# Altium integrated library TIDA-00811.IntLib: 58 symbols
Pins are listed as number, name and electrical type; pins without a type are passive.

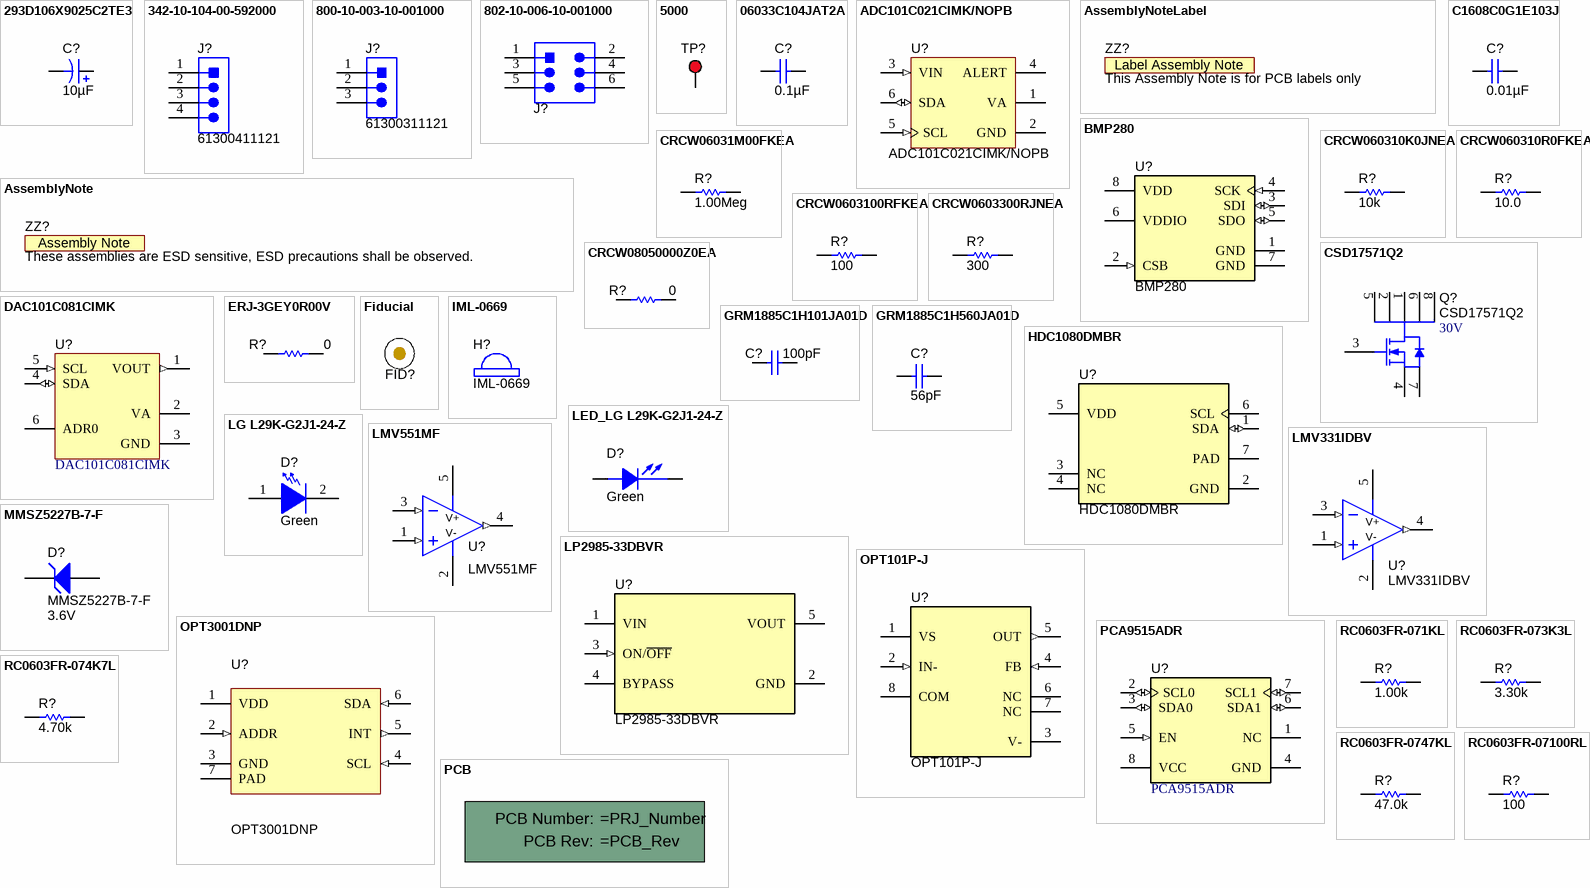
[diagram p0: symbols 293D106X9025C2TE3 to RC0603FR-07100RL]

## 293D106X9025C2TE3
designator C?  ValueDisplayed: 10µF  (hidden comment: 293D106X9025C2TE3)
CAP, TA, 10 µF, 25 V, +/- 10%, 1.5 ohm, SMD; Manufacturer: Vishay-Sprague; Polarized: Y; CompType: Capacitor; Value: 10uF; U/M: EA; Cap_F: 0.00001; Tolerance_%: 10; Value1: 1.5 ohm; VDC_V: 25; Value2: 25V; ESR_ohm: 1.5; IRMS_A: 0.27; TaMin_C: -55; TaMax_C: 125; Cap_Case: C; AEC Category: Q200
signal-integrity model Cap
simulation model Cap
footprint 6032-28 (Medium Density IPC based on Vishay Sprague 293D datasheet.)
pins: 1 +, 2 -

## 342-10-104-00-592000
designator J?, comment 61300411121
Header, 2.54mm, 4x1, Gold, TH; Manufacturer: Mill-Max; SymbolCreator: a0412235; Pitch_mm: 2.54; Gender: Male; Shrouded: N; Row_Count: 1
footprint Mill-Max_342-xx-104-00-592000
pins: 1, 2, 3, 4

## 800-10-003-10-001000
designator J?, comment 61300311121
Header, 100mil, 3x1, TH; Manufacturer: Mill-Max; SymbolCreator: a0799628; U/M: EA
footprint Mill-Max_800-10-003-10-001000
pins: 1, 2, 3
2 alternate drawings of the same symbol

## 802-10-006-10-001000
designator J?, comment 61300621121  (value not drawn)
Header, 2.54 mm, 3x2, Gold, TH; Manufacturer: Mill-Max; SymbolCreator: a0412235; Pitch_mm: 2.54; Gender: Male; Shrouded: N; Row_Count: 2
footprint Mill-Max_802-10-006-10-001000
pins: 1, 2, 3, 4, 5, 6

## 5000
designator TP?  (value not drawn)
Test Point, Miniature, Red, TH; Manufacturer: Keystone; CompType: Test Point Loop; U/M: EA
footprint Keystone5000
pins: 1

## 06033C104JAT2A
designator C?  ValueDisplayed: 0.1µF  (hidden comment: 06033C104JAT2A)
CAP, CERM, 0.1 µF, 25 V, +/- 5%, X7R, 0603; Manufacturer: AVX; Polarized: N; CompType: Capacitor; Value: 0.1uF; U/M: EA; Cap_F: 0.0000001; Tolerance_%: 5; ESR_ohm: 0.05; Value1: 0.05 ohm; VDC_V: 25; Value2: 25V; TaMin_C: -55; TaMax_C: 125; Cap_Case: 0603; AEC Category: Q200
signal-integrity model Cap
simulation model Cap
footprint 0603
footprint 0603M
footprint 0603L
footprint 0603_HV
footprint 0603S
pins: 1, 2

## ADC101C021CIMK/NOPB
designator U?
I2C-Compatible, 10-Bit Analog-to-Digital Converter (ADC) with Alert Pin, 6-pin Tiny SOT23, Pb-Free; Manufacturer: Texas Instruments; PackageTopMarking: X33C*XTT; PowerWise: N; CompType: ADC IC
footprint MK06A_N (SOT23, 6-Leads, Body 3.0x1.7mm, Pitch 0.95mm, Lead Span 2.9mm, IPC Medium Density)
footprint MK06A_L (SOT23, 6-Leads, Body 3.0x1.7mm, Pitch 0.95mm, Lead Span 2.9mm, IPC High Density)
footprint MK06A_M (SOT23, 6-Leads, Body 3.0x1.7mm, Pitch 0.95mm, Lead Span 2.9mm, IPC Low Density)
pins: 1 VA (power), 2 GND (power), 3 VIN (in), 4 ALERT (oc), 5 SCL (in), 6 SDA (io)

## AssemblyNote
designator ZZ?, comment These assemblies are ESD sensitive, ESD precautions shall be observed.  (no BOM)
SymbolCreator: codlsc; CompType: AssemblyNote
footprint AssemblyNote

## AssemblyNoteLabel
designator ZZ?, comment This Assembly Note is for PCB labels only  (no BOM)
SymbolCreator: a0412235
footprint AssemblyNoteLabel

## BMP280
designator U?
Digital Pressure Sensor, LGA8-2X2_5MM_0_65; Manufacturer: Bosch Solar Energy; SymbolCreator: Altium
footprint LGA8-2X2_5MM_0_65
pins: 1 GND (power), 2 CSB (in), 3 SDI (io), 4 SCK (in), 5 SDO (io), 6 VDDIO (power), 7 GND (power), 8 VDD (power)

## C1608C0G1E103J
designator C?  ValueDisplayed: 0.01µF  (hidden comment: C1608C0G1E103J)
CAP, CERM, 0.01uF, 25V, +/-5%, C0G/NP0, 0603; Manufacturer: TDK; Polarized: N; CompType: Capacitor; U/M: EA; Cap_F: 0.00000001; Tolerance_%: 5; Value1: Unknown; VDC_V: 25; TaMin_C: -55; TaMax_C: 125; Cap_Case: 0603
signal-integrity model Cap
simulation model Cap
footprint 0603
footprint 0603M
footprint 0603L
footprint 0603_HV
pins: 1, 2

## CRCW06031M00FKEA
designator R?  value 1.00Meg  (hidden comment: CRCW06031M00FKEA)
RES, 1.00Meg ohm, 1%, 0.1W, 0603; Manufacturer: Vishay-Dale; CompType: Resistor; Res_ohm: 1000000; Value_Code: 1M00; Tolerance_%: 1; Power_W: 0.1; VDC_V: 75; TempCo: 100 ppm/C; EIA_Code: E96; U/M: EA
signal-integrity model Resistor
simulation model Resistor
footprint 0603
footprint 0603M
footprint 0603L
footprint 0603_HV
footprint 0603S
pins: 1, 2

## CRCW060310K0JNEA
designator R?  ValueDisplayed: 10k  (hidden comment: CRCW060310K0JNEA)
RES, 10 k, 5%, 0.1 W, 0603; Manufacturer: Vishay-Dale; CompType: Resistor; Value: 10k; Res_ohm: 10000; Value_Code: 10k0; Tolerance_%: 5; Power_W: 0.1; Value2: 0.1W; VDC_V: 75; TempCo: 200 ppm/C; SizeArea_mm2: 1.28; SizeX_mm: 1.6; SizeY_mm: 0.8; SizeZ_mm: 1; EIA_Code: E24; U/M: EA; AEC Category: Q200
signal-integrity model Resistor
simulation model Resistor
footprint 0603
footprint 0603M
footprint 0603L
footprint 0603_HV
footprint 0603S
pins: 1, 2

## CRCW060310R0FKEA
designator R?  ValueDisplayed: 10.0  (hidden comment: CRCW060310R0FKEA)
RES, 10.0, 1%, 0.1 W, 0603; Manufacturer: Vishay-Dale; CompType: Resistor; Value: 10.0; Res_ohm: 10; Value_Code: 10R0; Tolerance_%: 1; Power_W: 0.1; Value2: 0.1W; VDC_V: 75; TempCo: 100 ppm/C; SizeArea_mm2: 1.28; SizeX_mm: 1.6; SizeY_mm: 0.8; EIA_Code: E96; U/M: EA; AEC Category: Q200
signal-integrity model Resistor
simulation model Resistor
footprint 0603
footprint 0603M
footprint 0603L
footprint 0603_HV
footprint 0603S
pins: 1, 2

## CRCW0603100RFKEA
designator R?  value 100  (hidden comment: CRCW0603100RFKEA)
RES, 100 ohm, 1%, 0.1W, 0603; Manufacturer: Vishay-Dale; CompType: Resistor; Value_Code: 100R; Tolerance_%: 1; Power_W: 0.1; VDC_V: 75; TempCo: 100 ppm/C; EIA_Code: E96; U/M: EA
signal-integrity model Resistor
simulation model Resistor
footprint 0603
footprint 0603M
footprint 0603L
footprint 0603_HV
pins: 1, 2

## CRCW0603300RJNEA
designator R?  value 300  (hidden comment: CRCW0603300RJNEA)
RES, 300 ohm, 5%, 0.1W, 0603; Manufacturer: Vishay-Dale; CompType: Resistor; Value_Code: 300R; Tolerance_%: 5; Power_W: 0.1; VDC_V: 75; TempCo: 200 ppm/C; EIA_Code: E24; U/M: EA
signal-integrity model Resistor
simulation model Resistor
footprint 0603 (0603 from SM-752 data)
footprint 0603M
footprint 0603L
footprint 0603_HV
footprint 0603
footprint 0603_HV
footprint 0603L
footprint 0603M
simulation model Resistor
signal-integrity model Resistor
pins: 1, 2

## CRCW08050000Z0EA
designator R?  ValueDisplayed: 0  (hidden comment: CRCW08050000Z0EA)
RES, 0, 5%, 0.125 W, 0805; Manufacturer: Vishay-Dale; CompType: Resistor; Value: 0; Value_Code: 0000; Tolerance_%: 5; Power_W: 0.125; Value2: 0.125W; VDC_V: 150; TempCo: 200 ppm/C; SizeArea_mm2: 2.5; SizeX_mm: 2; SizeY_mm: 1.25; SizeZ_mm: 1.45; EIA_Code: E24; U/M: EA; AEC Category: Q200
signal-integrity model Resistor
simulation model Resistor
footprint 0805_HV
footprint 0805_HV1
footprint 0805
footprint 0805M
footprint 0805L
pins: 1, 2

## CSD17571Q2
designator Q?  value 30V
MOSFET, N-CH, 30V, 22A, SON 2X2 MM; Manufacturer: TEXAS INSTRUMENTS; CompType: POWER MOSFET
footprint SON_CSD17571Q2 (SON, MOSFET, N-CH, 30V, 22A, SON 2X2 MM)
pins: 1 D, 2 D, 3 G, 4 S, 5 D, 6 D, 7 S, 8 D

## DAC101C081CIMK
designator U?
10-Bit Micro Power Digital-to-Analog Converter with an I2C-Compatible Interface, 6-pin Tiny SOT23; Manufacturer: Texas Instruments; PackageTopMarking: X85C*XTT; PowerWise: N; CompType: D/A Converter
footprint MK06A_N (SOT23, 6-Leads, Body 3.0x1.7mm, Pitch 0.95mm, Lead Span 2.9mm, IPC Medium Density)
footprint MK06A_L (SOT23, 6-Leads, Body 3.0x1.7mm, Pitch 0.95mm, Lead Span 2.9mm, IPC High Density)
footprint MK06A_M (SOT23, 6-Leads, Body 3.0x1.7mm, Pitch 0.95mm, Lead Span 2.9mm, IPC Low Density)
pins: 1 VOUT (out), 2 VA (power), 3 GND (power), 4 SDA (io), 5 SCL (in), 6 ADR0 (hiz)

## ERJ-3GEY0R00V
designator R?  ValueDisplayed: 0  (hidden comment: ERJ-3GEY0R00V)
RES, 0, 5%, 0.1 W, 0603; Manufacturer: Panasonic; CompType: Resistor; Value: 0; Value_Code: 0000; Tolerance_%: 5; Power_W: 0.1; Value2: 0.1W; VDC_V: 50; TempCo: 600 ppm/C; EIA_Code: E24; U/M: EA; AEC Category: Q200
signal-integrity model Resistor
simulation model Resistor
footprint 0603
footprint 0603M
footprint 0603L
footprint 0603_HV
footprint 0603S
pins: 1, 2

## Fiducial
designator FID?  (value not drawn)
Fiducial mark.  There is nothing to buy or mount.; SymbolCreator: codlsc
footprint Fiducial10-30
footprint Fiducial10-20
footprint Fiducial15-30
footprint Fiducial20-40
footprint Fiducial6.4-20

## GRM1885C1H101JA01D
designator C?  ValueDisplayed: 100pF  (hidden comment: GRM1885C1H101JA01D)
CAP, CERM, 100 pF, 50 V, +/- 5%, C0G/NP0, 0603; Manufacturer: MuRata; Polarized: N; CompType: Capacitor; Value: 100pF; U/M: EA; Cap_F: 0.0000000001; Tolerance_%: 5; Value1: Unknown; VDC_V: 50; Value2: 50V; TaMin_C: -55; TaMax_C: 125; Cap_Case: 0603; SizeArea_mm2: 1.28; SizeAreaWB_mm2: 4.68; SizeX_mm: 1.6; SizeY_mm: 0.8; SizeZ_mm: 1; AEC Category: Q200
signal-integrity model Cap
simulation model Cap
footprint 0603
footprint 0603M
footprint 0603L
footprint 0603_HV
footprint 0603S
pins: 1, 2

## GRM1885C1H560JA01D
designator C?  ValueDisplayed: 56pF  (hidden comment: GRM1885C1H560JA01D)
CAP, CERM, 56 pF, 50 V, +/- 5%, C0G/NP0, 0603; Manufacturer: MuRata; Polarized: N; CompType: Capacitor; Value: 56pF; U/M: EA; Cap_F: 0.000000000056; Tolerance_%: 5; Value1: Unknown; VDC_V: 50; Value2: 50V; TaMin_C: -55; TaMax_C: 125; Cap_Case: 0603; SizeArea_mm2: 1.28; SizeAreaWB_mm2: 4.68; SizeX_mm: 1.6; SizeY_mm: 0.8; SizeZ_mm: 1; AEC Category: Q200
signal-integrity model Cap
simulation model Cap
footprint 0603
footprint 0603M
footprint 0603L
footprint 0603_HV
footprint 0603S
pins: 1, 2

## HDC1080DMBR
designator U?
Low Power, High Accuracy Digital Humidity Sensor with Temperature Sensor, DMB0006A; Alternate PartNumber: HDC1080DMBT; Manufacturer: Texas Instruments; SymbolCreator: a0411947; CompType: IC; U/M: EA
footprint DMB0006A (TI)
footprint DMB0006A_NV
pins: 1 SDA (io), 2 GND (power), 3 NC, 4 NC, 5 VDD (power), 6 SCL (oc), 7 PAD (power)

## IML-0669
designator H?
Lens, Ceiling Mount, TH; Manufacturer: MuRata; SymbolCreator: Altium
footprint Murata_IML-0669 (Pyroelectric Infrared Lens, TH)

## LED_LG L29K-G2J1-24-Z
designator D?  value Green  (hidden comment: LED_LG L29K-G2J1-24-Z)
LED SmartLED Green 570NM; Manufacturer: OSRAM; SymbolCreator: x0120606
footprint LED0603AA
pins: 1 C, 2 A

## LG L29K-G2J1-24-Z
designator D?  value Green  (hidden comment: LG L29K-G2J1-24-Z)
LED, Green, SMD; Manufacturer: OSRAM; Vf_V: 1.7; Value2: 1.7V; Io_A: 0.002; Tjmax_C: 110; Value1: W; U/M: EA
signal-integrity model Diode
footprint LG L29K_GREEN
pins: 1 A, 2 K

## LMV331IDBV
designator U?
Single General Purpose Low-Voltage Comparator, DBV0005A; Manufacturer: Texas Instruments; SymbolCreator: a0411595; CompType: OpAmp IC
footprint DBV0005A_N
footprint DBV0005A_M
footprint DBV0005A_L
simulation model lmv331 (SUBCKT)
pins: 1 IN+ (in), 2 V- (power), 3 IN- (in), 4 OUT (out), 5 V+ (power)
1 alternate drawing of the same symbol

## LMV551MF
designator U?
3MHz Single Micropower R-R Out Op Amp; Manufacturer: TI; Characteristics: LMV551MF 3MHz Single Micropower R-R Out Op Amp; CompType: OpAmp IC; TaMin_C: -40.0; TaMax_C: 125.0; PowerWise: N
3D model MF05A
footprint MF05A_L
footprint MF05A_M
footprint MF05A_N
simulation model LMV551 (SUBCKT)
pins: 1 IN+ (in), 2 V- (power), 3 IN- (in), 4 OUT (out), 5 V+ (power)
1 alternate drawing of the same symbol

## LP2985-33DBVR
designator U?
100-mA ULTRA-LOW DROPOUT REGULATOR WITH SHUTDOWN, DBV0005A; Alternate PartNumber: LP2985-33DBVT; Manufacturer: Texas Instruments; SymbolCreator: Altium; CompType: IC; U/M: EA
footprint DBV0005A_N (SOT23, 5-Leads, Body 2.9x1.6mm, Pitch 0.95mm, Lead Span 2.8mm, IPC Medium Density)
footprint DBV0005A_M
footprint DBV0005A_L
pins: 1 VIN (power), 2 GND (power), 3 ON/~{OFF} (in), 4 BYPASS, 5 VOUT (power)

## MMSZ5227B-7-F
designator D?  value 3.6V
Diode, Zener, 3.6 V, 500 mW, SOD-123; Manufacturer: Diodes Inc.; SymbolCreator: a0412235; U/M: EA; Power_W: 0.5; Vz_V: 3.6; Value1: 0.5W; RJA_CperW: 350; AEC Category: Q101
signal-integrity model Diode
footprint SOD-123
pins: 1 K, 2 A

## OPT101P-J
designator U?
Monolithic Photodiode and Single-Supply Transimpedance Amplifier, DTL0008A; Manufacturer: Texas Instruments; SymbolCreator: Altium; CompType: IC; U/M: EA
footprint DTL0008A_N
footprint DTL0008A_M
footprint DTL0008A_L
pins: 1 VS (power), 2 IN- (in), 3 V- (power), 4 FB (in), 5 OUT (out), 6 NC, 7 NC, 8 COM

## OPT3001DNP
designator U?
Ambient Light Sensor, DNP0006A; Manufacturer: Texas Instruments; SymbolCreator: a0411947; CompType: IC; U/M: EA
footprint DNP0006A (DFN-6 2x2mm)
pins: 1 VDD (power), 2 ADDR (in), 3 GND (power), 4 SCL (in), 5 INT (out), 6 SDA (in), 7 PAD
1 alternate drawing of the same symbol

## PCA9515ADR
designator U?
Dual Bidirectional I2C Bus and SMBus Repeater, 2 Channel Width, 2.3 to 3.6 V, -40 to 85 degC, 8-pin SOIC (D), Green (RoHS & no Sb/Br); Manufacturer: Texas Instruments; Alternate PartNumber: Equivalent; SubFamily: I2C Hub, Buffer, Repeater; No. of Outputs: 2; VCC(Max)(V): 3.6; VCC(Min)(V): 2.3; Max Frequency(kHz): 400; Vcc range(V): 2.3 to 5.5; 5V Tolerant I/O: Yes
footprint D0008A_N (SOIC, 8-Leads, Body 4.9x3.9mm, Pitch 1.27mm, IPC Medium Density)
footprint D0008A_L (SOIC, 8-Leads, Body 4.9x3.9mm, Pitch 1.27mm, IPC High Density)
footprint D0008A_M (SOIC, 8-Leads, Body 4.9x3.9mm, Pitch 1.27mm, IPC Low Density)
pins: 1 NC "No internal connection", 2 SCL0 (io) "Serial clock bus 0", 3 SDA0 (io) "Serial data bus 0", 4 GND (power) "Supply ground", 5 EN (in) "Active-high repeater enable input", 6 SDA1 (io) "Serial data bus 1", 7 SCL1 (io) "Serial clock bus 1", 8 VCC (power) "Supply power"

## PCB
designator !PCB?, comment Printed Circuit Board  (value not drawn)  (mechanical)
Manufacturer: Any; SymbolCreator: a0412235; CompType: PCB
1 alternate drawing of the same symbol

## RC0603FR-071KL
designator R?  ValueDisplayed: 1.00k  (hidden comment: RC0603FR-071KL)
RES, 1.00 k, 1%, 0.1 W, 0603; Manufacturer: Yageo America; CompType: Resistor; Value: 1.00k; Res_ohm: 1000; Value_Code: 1k00; Tolerance_%: 1; Power_W: 0.1; Value2: 0.1W; VDC_V: 150; TempCo: 200 ppm/C; EIA_Code: E96; U/M: EA; AEC Category: Q200
signal-integrity model Resistor
simulation model Resistor
footprint 0603
footprint 0603M
footprint 0603L
footprint 0603_HV
footprint 0603S
pins: 1, 2

## RC0603FR-073K3L
designator R?  ValueDisplayed: 3.30k  (hidden comment: RC0603FR-073K3L)
RES, 3.30 k, 1%, 0.1 W, 0603; Manufacturer: Yageo America; CompType: Resistor; Value: 3.30k; Res_ohm: 3300; Value_Code: 3k30; Tolerance_%: 1; Power_W: 0.1; Value2: 0.1W; VDC_V: 150; TempCo: 200 ppm/C; U/M: EA; AEC Category: Q200
signal-integrity model Resistor
simulation model Resistor
footprint 0603
footprint 0603M
footprint 0603L
footprint 0603_HV
footprint 0603S
pins: 1, 2

## RC0603FR-074K7L
designator R?  ValueDisplayed: 4.70k  (hidden comment: RC0603FR-074K7L)
RES, 4.70 k, 1%, 0.1 W, 0603; Manufacturer: Yageo America; CompType: Resistor; Value: 4.70k; Res_ohm: 4700; Value_Code: 4k70; Tolerance_%: 1; Power_W: 0.1; Value2: 0.1W; VDC_V: 150; TempCo: 200 ppm/C; U/M: EA; AEC Category: Q200
signal-integrity model Resistor
simulation model Resistor
footprint 0603
footprint 0603M
footprint 0603L
footprint 0603_HV
footprint 0603S
pins: 1, 2

## RC0603FR-0747KL
designator R?  ValueDisplayed: 47.0k  (hidden comment: RC0603FR-0747KL)
RES, 47.0 k, 1%, 0.1 W, 0603; Manufacturer: Yageo America; CompType: Resistor; Value: 47.0k; Res_ohm: 47000; Value_Code: 47k0; Tolerance_%: 1; Power_W: 0.1; Value2: 0.1W; VDC_V: 150; TempCo: 200 ppm/C; U/M: EA; AEC Category: Q200
signal-integrity model Resistor
simulation model Resistor
footprint 0603
footprint 0603M
footprint 0603L
footprint 0603_HV
footprint 0603S
pins: 1, 2

## RC0603FR-07100RL
designator R?  ValueDisplayed: 100  (hidden comment: RC0603FR-07100RL)
RES, 100, 1%, 0.1 W, 0603; Manufacturer: Yageo America; CompType: Resistor; Value: 100; Value_Code: 100R; Tolerance_%: 1; Power_W: 0.1; Value2: 0.1W; VDC_V: 150; TempCo: 200 ppm/C; EIA_Code: E96; U/M: EA; AEC Category: Q200
signal-integrity model Resistor
simulation model Resistor
footprint 0603
footprint 0603M
footprint 0603L
footprint 0603_HV
footprint 0603S
pins: 1, 2

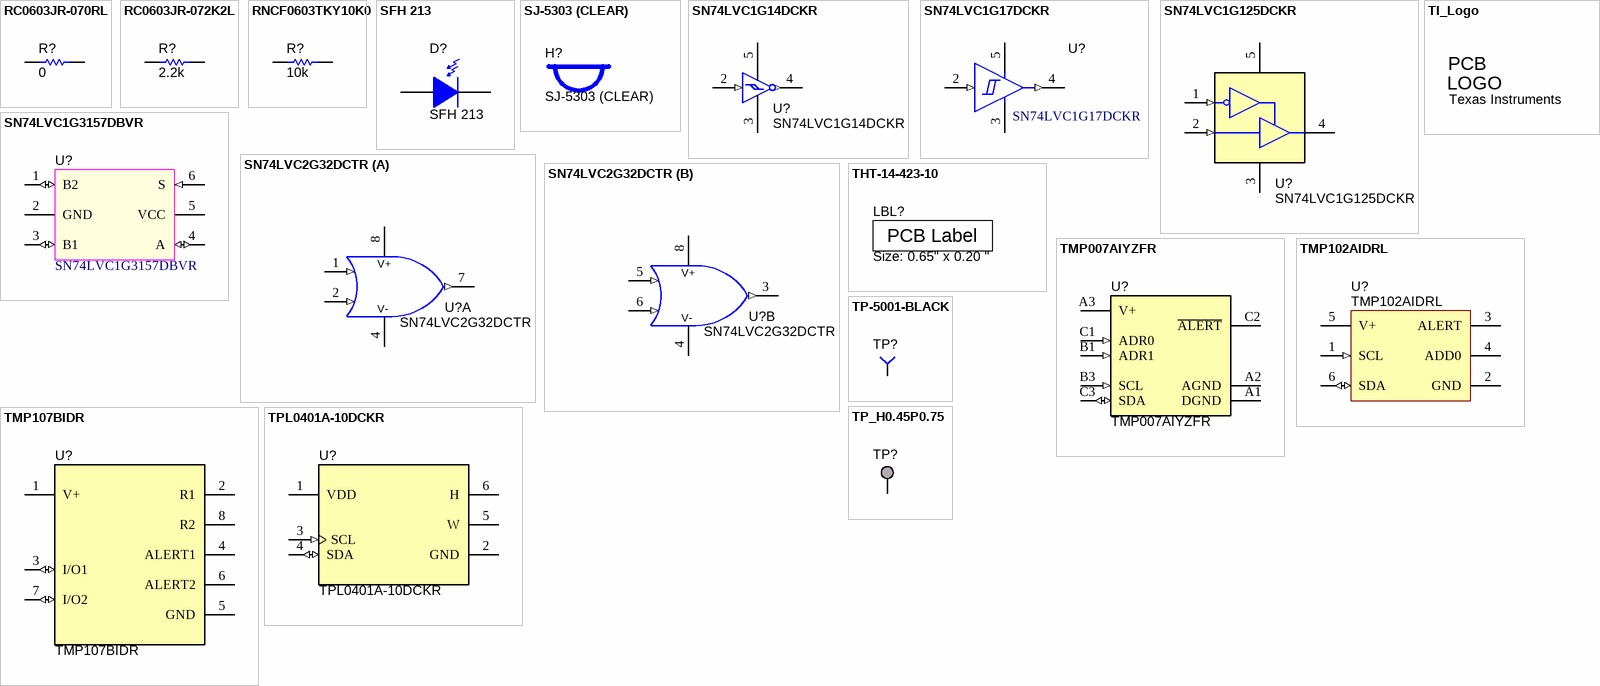
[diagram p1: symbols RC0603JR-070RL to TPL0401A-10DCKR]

## RC0603JR-070RL
designator R?  ValueDisplayed: 0  (hidden comment: RC0603JR-070RL)
RES, 0, 5%, 0.1 W, 0603; Manufacturer: Yageo America; CompType: Resistor; Value: 0; Value_Code: 0000; Tolerance_%: 5; Power_W: 0.1; Value2: 0.1W; VDC_V: 50; TempCo: 200 ppm/C; EIA_Code: E24; U/M: EA; AEC Category: Q200
signal-integrity model Resistor
simulation model Resistor
footprint 0603
footprint 0603M
footprint 0603L
footprint 0603_HV
footprint 0603S
pins: 1, 2

## RC0603JR-072K2L
designator R?  ValueDisplayed: 2.2k  (hidden comment: RC0603JR-072K2L)
RES, 2.2 k, 5%, 0.1 W, 0603; Manufacturer: Yageo America; CompType: Resistor; Value: 2.2k; Res_ohm: 2200; Value_Code: 2k20; Tolerance_%: 5; Power_W: 0.1; Value2: 0.1W; VDC_V: 50; TempCo: 100 ppm/C; SizeArea_mm2: 1.28; SizeX_mm: 1.6; SizeY_mm: 0.8; SizeZ_mm: 1; EIA_Code: E24; U/M: EA; AEC Category: Q200
signal-integrity model Resistor
simulation model Resistor
footprint 0603
footprint 0603M
footprint 0603L
footprint 0603_HV
footprint 0603S
pins: 1, 2

## RNCF0603TKY10K0
designator R?, comment value 10k  (hidden comment: CRCW060310K0FKEA)
RES, 10.0k ohm, 1%, 0.1W, 0603; Manufacturer: Stackpole Electronics Inc; CompType: Resistor; Res_ohm: 10000; Value_Code: 10k0; Tolerance_%: 0.01; Value1: 0.01%; Power_W: 0.063; Value2: 0.063W; VDC_V: 50; TempCo: 5 ppm/C; U/M: EA
signal-integrity model Resistor
simulation model Resistor
footprint 0603
footprint 0603M
footprint 0603L
footprint 0603_HV
pins: 1, 2

## SFH 213
designator D?
Silicon PIN Photodiode, TH; Manufacturer: OSRAM; SymbolCreator: Altium
footprint SFH_213
pins: 1 A, 2 C

## SJ-5303 (CLEAR)
designator H?
Bumpon, Hemisphere, 0.44 X 0.20, Clear; Manufacturer: 3M; SymbolCreator: a0412235
footprint Bumpon_SJ5003Transparent

## SN74LVC1G14DCKR
designator U?
SINGLE SCHMITT-TRIGGER INVERTER, DCK0005A; Alternate PartNumber: SN74LVC1G14DCKT; Manufacturer: Texas Instruments; SymbolCreator: a0799628; CompType: IC; U/M: EA
footprint DCK0005A_N
footprint DCK0005A_M
footprint DCK0005A_L
pins: 2 A (in), 3 GND (power), 4 Y (out), 5 VCC (power)

## SN74LVC1G17DCKR
designator U?
SINGLE SCHMITT-TRIGGER BUFFER, DCK0005A (SOT-5); Alternate PartNumber: SN74LVC1G17DCKT; Manufacturer: Texas Instruments; SymbolCreator: a0799628; SizeArea_mm2: 4.2; SizeAreaWB_mm2: 9.3; SizeX_mm: 2.1; SizeY_mm: 2; SizeZ_mm: 1.1; CompType: IC; U/M: EA
footprint DCK0005A_N
footprint DCK0005A_M
footprint DCK0005A_L
pins: 2 A (in), 3 GND (power), 4 Y (out), 5 VCC (power)

## SN74LVC1G125DCKR
designator U?
Single Bus Buffer Gate With 3-State Output, DCK0005A; Alternate PartNumber: SN74LVC1G125DCKT; Manufacturer: Texas Instruments; SymbolCreator: Altium; CompType: IC; U/M: EA
footprint DCK0005A_N (SOT353, 5-Leads, Body 2x1.3mm, Pitch 0.65mm, Lead Span 2.1mm, IPC Medium Density)
footprint DCK0005A_M
footprint DCK0005A_L
pins: 1 ~{OE} (in), 2 A (in), 3 GND (power), 4 Y (hiz), 5 VCC (power)

## SN74LVC1G3157DBVR
designator U?
IC, SWITCH, SPDT, SOT23-6; Manufacturer: TEXAS INSTRUMENTS; SymbolCreator: x0199378
footprint SOT23-6 (IC DAC R-R LP 12BIT SOT23-6)
pins: 1 B2 (io), 2 GND (power), 3 B1 (io), 4 A (io), 5 VCC (power), 6 S (in)

## SN74LVC2G32DCTR
designator U?
Dual 2-Input Positive-OR Gate, DCT0008A; Manufacturer: Texas Instruments; SymbolCreator: a0411947; CompType: IC; U/M: EA
footprint DCT0008A_N
footprint DCT0008A_M
footprint DCT0008A_L
pins on every part: 4 GND (power), 8 VCC (power)
part A pins: 1 1A (in), 2 1B (in), 7 1Y (out)
part B pins: 3 2Y (out), 5 2A (in), 6 2B (in)

## THT-14-423-10
designator LBL?, comment Size: 0.65" x 0.20 "
Thermal Transfer Printable Labels, 0.650" W x 0.200" H - 10,000 per roll; Manufacturer: Brady; PartNumber: THT-14-423-10; SymbolCreator: a0412235; CompType: Label
footprint Label_650x200

## TI_Logo
designator Logo?, comment Texas Instruments  (no BOM)
Texas Instrument Corporate Signature; SymbolCreator: codlsc
footprint TI_Stacked_SolderMask_Medium
footprint TI_Stacked_SolderMask_Small
footprint TI_Stacked_Overlay_Medium
footprint TI_Stacked_Overlay_Small
footprint TI_Horizontal_SolderMask_Medium
footprint TI_Horizontal_SolderMask_Small
footprint TI_Horizontal_Overlay_Medium
footprint TI_Horizontal_Overlay_Small
footprint TI_Symbol_SolderMask_Small
footprint TI_Symbol_Overlay_Medium
footprint TI_Symbol_Overlay_Small
footprint TI_Symbol_SolderMask_Medium

## TMP007AIYZFR
designator U?
Infrared Thermopile Sensor with Integrated Math Engine, YZF0008AEAE; Alternate PartNumber: TMP007AIYZFT; Manufacturer: Texas Instruments; SymbolCreator: a0411947; SizeArea_mm2: 2.359296; SizeAreaWB_mm2: 6.431296; SizeX_mm: 1.536; SizeZ_mm: 0.625; CompType: IC; U/M: EA
footprint YZF0008AEAE
pins: A1 DGND (power), A2 AGND (power), A3 V+ (power), B1 ADR1 (in), B3 SCL (in), C1 ADR0 (in), C2 ~{ALERT} (oc), C3 SDA (io)

## TMP102AIDRL
designator U?
Low Power Digital Temperature Sensor With SMBus/Two-Wire Serial Interface in SOT563, DRL0006A; Alternate Manufacturer: None; Manufacturer: Texas Instruments; SymbolCreator: a0411947; CompType: IC; U/M: EA
footprint DRL0006A_N (SOTFL, 6-Flat Leads, Body 1.2x1.6x0.6mm, Pitch 0.5mm, IPC Medium Density)
footprint DRL0006A_M
footprint DRL0006A_L
pins: 1 SCL (in), 2 GND (power), 3 ALERT (oc), 4 ADD0, 5 V+ (power), 6 SDA (io)

## TMP107BIDR
designator U?
TMP107B, D0008A; Manufacturer: Texas Instruments; SymbolCreator: Altium; CompType: IC; U/M: EA
footprint D0008A_N (SOIC, 8-Leads, Body 4.9x3.9mm, Pitch 1.27mm, IPC Medium Density)
footprint D0008A_M
footprint D0008A_L
pins: 1 V+ (power), 2 R1, 3 I/O1 (io), 4 ALERT1, 5 GND (power), 6 ALERT2, 7 I/O2 (io), 8 R2

## TP-5001-BLACK
designator TP?  (value not drawn)
Test Point,  Black, Thru Hole Color Keyed; Manufacturer: Keystone; PartNumber: 5001; area: 10.000; Value: 5001
footprint TH-40
pins: 1

## TP_H0.45P0.75
designator TP?, comment TESTPOINT  (value not drawn)  (no BOM)
Manufacturer: Texas Instruments; PartNumber: TP_H0.45P0.75; CompType: Pad
footprint TP_H045P075 (TP_H0.45P0.75)
pins: 1

## TPL0401A-10DCKR
designator U?
128 TAPS Single Channel Digital Potentiometer with I2C Interface, DCK0006A; Manufacturer: Texas Instruments; SymbolCreator: Altium; CompType: IC; U/M: EA
footprint DCK0006A_N
footprint DCK0006A_M
footprint DCK0006A_L
pins: 1 VDD (power) "Positive Supply Voltage", 2 GND (power) "Ground", 3 SCL (in) "I2C Clock", 4 SDA (io) "I2C Data", 5 W "Wiper terminal", 6 H "High terminal"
